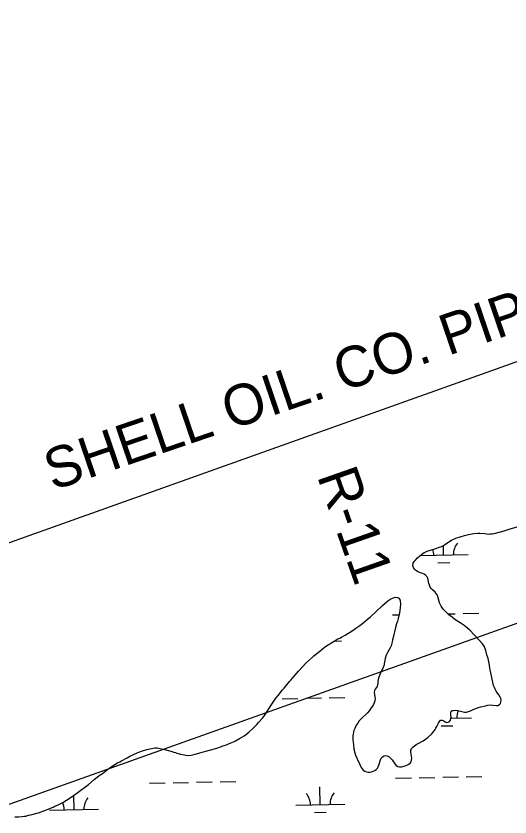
# Model space of a CAD drawing. Extents: x 3989314 to 4027622, y 243956 to 270014.
# Drawn here: x 3999415 to 4000421, y 258108 to 259739 of the extents above; entities that cross this region are included whole.
import ezdxf

# ---------------------------------------------------------------- set-up
doc = ezdxf.new("R2010")
doc.units = 0
for name, color, linetype in [('V-RIVR-EDGE', 7, 'Continuous'), ('V-RIVR-RANG-IDEN', 7, 'Continuous'), ('V-UTIL-IDEN', 7, 'Continuous'), ('V-UTIL-LINE', 7, 'Continuous'), ('V-WETL-SWMP', 7, 'Continuous')]:
    doc.layers.add(name, color=color, linetype=linetype)

msp = doc.modelspace()

# ---------------------------------------------------------------- linework, layer by layer
at = {"layer": 'V-RIVR-EDGE'}
for points in [[(4000224.3, 258624.6), (4000226.1, 258628.2), (4000228.1, 258630.5), (4000233.1, 258635.6), (4000237.8, 258639.8), (4000240.9, 258642.4), (4000246.7, 258646.3), (4000249.5, 258647.8), (4000252.4, 258649), (4000270.4, 258654.7), (4000277.7, 258657.2), (4000281.6, 258658.8), (4000286, 258661), (4000289.8, 258663.3), (4000298.9, 258669.5), (4000302.2, 258671.6), (4000311.2, 258675.6), (4000319.9, 258678.6), (4000328.7, 258681.1), (4000336.5, 258683), (4000347.8, 258685.1), (4000355.3, 258685.7), (4000360.1, 258685.7), (4000369.9, 258684.9), (4000373.8, 258684.3), (4000377.8, 258684), (4000381.2, 258684.2), (4000385.2, 258684.5), (4000389.2, 258685.2), (4000401.7, 258688.4), (4000409.5, 258690.7), (4000419.9, 258694.2), (4000435.7, 258698.6)], [(4000244.1, 258262.5), (4000253.6, 258269.8), (4000261.7, 258277.3), (4000264.4, 258280), (4000266.8, 258282.9), (4000268.9, 258285.8), (4000270.5, 258288.4), (4000272.4, 258292.2), (4000275.6, 258299), (4000277.4, 258302.1), (4000279.6, 258304.7), (4000283, 258305.1), (4000286.2, 258303.9), (4000289.1, 258301.5), (4000291.8, 258300.2), (4000295.1, 258300.7), (4000298.2, 258302.1), (4000299.9, 258304.9), (4000300.8, 258308.2), (4000301.2, 258311.4), (4000300.8, 258315.1), (4000300.7, 258318.4), (4000301, 258321.9), (4000303.4, 258324.3), (4000307.2, 258324.8), (4000310.5, 258325.1), (4000315, 258324.7), (4000328.7, 258321.3), (4000332.6, 258321.3), (4000340.9, 258323.9), (4000344.9, 258325.8), (4000353.3, 258329.3), (4000357.3, 258330.6), (4000361.7, 258331.9), (4000368.3, 258333.3), (4000371.4, 258334.3), (4000375.9, 258335.4), (4000382.6, 258336), (4000386.1, 258335.8), (4000393.2, 258334.5), (4000396.7, 258335.1), (4000400.1, 258336.5), (4000402.1, 258338.7), (4000403, 258341.9), (4000403.2, 258345.4), (4000402.6, 258348.8), (4000401.4, 258352), (4000398.9, 258356.2), (4000395.8, 258360), (4000393, 258364.2), (4000390.8, 258368.3), (4000389.5, 258371.2), (4000387.9, 258375.4), (4000384.1, 258392.1), (4000382.4, 258401.5), (4000380.5, 258410.9), (4000379.6, 258417), (4000376.6, 258430.7), (4000374.3, 258438), (4000372.1, 258446.6), (4000370.7, 258450.5), (4000369.1, 258454.2), (4000367.3, 258457.6), (4000364.9, 258461.2), (4000359.5, 258467.3), (4000339.2, 258488.1), (4000331.3, 258495.2), (4000327.8, 258497.9), (4000324.1, 258500.6), (4000320.1, 258503.1), (4000309.1, 258510.3), (4000303.3, 258514.6), (4000297, 258519.8), (4000291.9, 258524.4), (4000286, 258530.6), (4000283.8, 258533.3), (4000281.2, 258537), (4000279, 258541), (4000277.9, 258544.1), (4000275.2, 258553.8), (4000274, 258557.3), (4000272.8, 258560.1), (4000268.8, 258565.7), (4000263.5, 258570.7), (4000261, 258573.4), (4000258.8, 258576.1), (4000257.1, 258579.6), (4000256.1, 258583.5), (4000254.8, 258590.5), (4000253.7, 258594.1), (4000252.2, 258597.2), (4000249.5, 258599.8), (4000246.4, 258602.1), (4000242.8, 258603.8), (4000237.1, 258606), (4000233.1, 258607.8), (4000229.5, 258609.9), (4000226.6, 258612.4), (4000224.4, 258615.7), (4000223.5, 258620.1), (4000224.3, 258624.6)], [(3999490.1, 258127.6), (3999493.5, 258129.4), (3999501.9, 258133.3), (3999509.7, 258137.3), (3999525.2, 258146.6), (3999538.8, 258155.9), (3999562, 258174.1), (3999573.7, 258184), (3999579.9, 258188.9), (3999584.3, 258192.3), (3999590.5, 258196.5), (3999600.7, 258204.5), (3999610.8, 258211.3), (3999621.5, 258217.7), (3999625.8, 258219.8), (3999629.5, 258222.1), (3999641.2, 258228.4), (3999647.6, 258232.2), (3999651.1, 258233.7), (3999654, 258235.3), (3999661.7, 258238.6), (3999664.8, 258239.9), (3999672.6, 258242.7), (3999681.2, 258245.3), (3999690.4, 258247.5), (3999697.6, 258248.4), (3999702, 258248.7), (3999720.1, 258244.5), (3999732.6, 258241), (3999735.6, 258240), (3999739.5, 258238.9), (3999742.3, 258237.9), (3999749.8, 258235.8), (3999757.6, 258234), (3999763.6, 258233.1), (3999771.8, 258233.9), (3999779.7, 258235.7), (3999796.7, 258240.7), (3999801.4, 258241.7), (3999818.9, 258246.4), (3999826.2, 258248.6), (3999829.3, 258249.9), (3999833.2, 258251.1), (3999836.1, 258252.4), (3999843.6, 258255), (3999847.8, 258256.8), (3999850.7, 258258.4), (3999857.7, 258260.8), (3999861.7, 258262.8), (3999870.1, 258267.5), (3999880.6, 258273.8), (3999890, 258281.2), (3999895.8, 258286.4), (3999903.5, 258294), (3999905.5, 258296.2), (3999908.6, 258300.1), (3999916.9, 258309), (3999919.5, 258312.4), (3999924.8, 258320.2), (3999934.5, 258335.3), (3999944.3, 258349.4), (3999948.8, 258355.4), (3999958, 258366.5), (3999961.1, 258370), (3999966.6, 258376.9), (3999972.2, 258383.7), (3999975, 258386.7), (3999981.4, 258394.7), (3999990.3, 258405), (4000005.9, 258421.4), (4000011.9, 258427.2), (4000018.4, 258432.8), (4000021.8, 258435.9), (4000033.8, 258445.8), (4000043.5, 258453.3), (4000050.8, 258458.6), (4000059.4, 258463.9), (4000063, 258465.8), (4000069.3, 258469.6), (4000074.2, 258472.1), (4000077.6, 258474.2), (4000085.3, 258478.3), (4000099.6, 258486.7), (4000107.4, 258492), (4000115.2, 258497.7), (4000121.1, 258502.3), (4000130.8, 258510.5), (4000136.1, 258514.6), (4000148.4, 258526.3), (4000161.3, 258538.2), (4000172.7, 258547.9), (4000178.7, 258552), (4000185.6, 258554.7), (4000188.9, 258555.2), (4000192.1, 258554.9), (4000194.8, 258553.2), (4000196.7, 258550.6), (4000197.6, 258547.6), (4000198.2, 258541.9), (4000197.6, 258533.8), (4000196.1, 258523.3)], [(4000196.1, 258523.3), (4000193.5, 258511.8), (4000191.9, 258506.8), (4000189.9, 258501.2), (4000187.7, 258493.5), (4000183, 258473.5), (4000182, 258468.7), (4000181.3, 258464.4), (4000179.2, 258456.4), (4000177.4, 258452.2), (4000171.5, 258442.5), (4000169.4, 258438.6), (4000168, 258435), (4000166.7, 258430.3), (4000164.1, 258415.4), (4000163.1, 258412), (4000161, 258407.7), (4000157.2, 258401.3), (4000153.9, 258392.5), (4000152.6, 258388.1), (4000152.1, 258384.4), (4000151.9, 258380.2), (4000151.4, 258377.1), (4000150.4, 258373.5), (4000148.7, 258370.7), (4000146.6, 258368.1), (4000145.1, 258365.3), (4000144.7, 258361.6), (4000145.2, 258357.5), (4000146.1, 258352.7), (4000146.4, 258348.6), (4000145.7, 258344.2), (4000144.4, 258339.9), (4000142.9, 258336.8), (4000140.4, 258332.7), (4000137.3, 258328.2), (4000134.7, 258324.8), (4000129.9, 258319.1), (4000118.5, 258308.3), (4000116.5, 258306.1), (4000114, 258303.3), (4000111.1, 258299.1), (4000108.1, 258294.5), (4000105, 258288), (4000103.4, 258283.9), (4000102.3, 258280.4), (4000101.6, 258276.7), (4000101.1, 258272.7), (4000101.1, 258264.7), (4000101.5, 258259.2), (4000102.1, 258255.5), (4000103.3, 258246), (4000105.2, 258238.6), (4000106.7, 258233.5), (4000109.7, 258226.3), (4000115.3, 258214.4), (4000116.8, 258211.4), (4000117.8, 258208.6), (4000119.9, 258205.6), (4000122.2, 258203.3), (4000125.5, 258200.9), (4000128.7, 258199.5), (4000132, 258198.9), (4000135.8, 258199.3), (4000138.9, 258199.9), (4000142.4, 258200.9), (4000146, 258202.5), (4000148.6, 258204.7), (4000151.3, 258207.3), (4000152.8, 258210.1), (4000154.3, 258213.3), (4000157.4, 258224.1), (4000159.1, 258227.3), (4000161.8, 258229.9), (4000165, 258232.1), (4000168.2, 258233), (4000171.3, 258232.2), (4000175.2, 258229.9), (4000178.9, 258226.4), (4000181.1, 258223.8), (4000184, 258220), (4000186.4, 258216.3), (4000189.5, 258212.7), (4000192.9, 258210.5), (4000196.4, 258209.8), (4000200.3, 258209.8), (4000207.6, 258211.6), (4000211.4, 258213), (4000215.1, 258215.2), (4000217.6, 258217.4), (4000219.6, 258220.1), (4000220.8, 258223.2), (4000221.2, 258227.4), (4000219.1, 258239.6), (4000219.5, 258243.4), (4000220.9, 258246.9), (4000223.5, 258249.8), (4000225.7, 258251.9), (4000230, 258255.1), (4000232.7, 258256.7), (4000244.1, 258262.5)], [(3999411.8, 258108.2), (3999419.7, 258107.8), (3999427.2, 258108.4), (3999431.2, 258109.1), (3999434.8, 258109.7), (3999439.7, 258111.1), (3999445, 258112.3), (3999457.1, 258115.6), (3999460.1, 258116.3), (3999474.8, 258121.3), (3999490.1, 258127.6)]]:
    msp.add_lwpolyline(points, dxfattribs=at)
at = {"layer": 'V-UTIL-LINE'}
for points in [[(3993476.2, 256555.4), (4009243.9, 262176.3), (4010284.4, 262316.3), (4011271.4, 262462.6)], [(4011371.2, 261859.1), (4011335.1, 261835.4), (4010585.7, 261810.1), (4009561, 261669.6), (4009556.2, 261668.8), (4009323.1, 261637.1), (4006559.3, 260668.5), (4004279, 259872), (3996043.1, 256937.7), (3993486.8, 256012.2)]]:
    msp.add_lwpolyline(points, dxfattribs=at)
at = {"layer": 'V-WETL-SWMP'}
for p, q in [((4000286.1, 258641.4), (4000285.7, 258660.8)), ((4000238.5, 258640.5), (4000336.1, 258642.4)), ((4000274.4, 258625.7), (4000298.4, 258626.2)), ((4000181.6, 258519.2), (4000195.2, 258519.5)), ((4000295.1, 258521.5), (4000309.6, 258521.8)), ((4000325.6, 258522.1), (4000357.6, 258522.7)), ((4000063.5, 258466.1), (4000078.1, 258466.4)), ((4000039.5, 258450.2), (4000040.4, 258450.2)), ((4000053, 258350.5), (4000085, 258351.1)), ((3999957, 258348.5), (3999989, 258349.2)), ((4000005, 258349.5), (4000037, 258350.1)), ((4000300.9, 258309), (4000342.7, 258309.8)), ((4000281, 258293.1), (4000305, 258293.6)), ((4000188.3, 258186.6), (4000220.3, 258187.3)), ((4000236.3, 258187.6), (4000268.3, 258188.2)), ((4000284.3, 258188.5), (4000316.2, 258189.2)), ((4000332.2, 258189.5), (4000364.2, 258190.1)), ((3999686.5, 258176.6), (3999718.5, 258177.3)), ((3999734.5, 258177.6), (3999766.4, 258178.2)), ((3999782.4, 258178.5), (3999814.4, 258179.2)), ((3999830.4, 258179.5), (3999862.4, 258180.1)), ((4000034.7, 258132.8), (4000034, 258168.8)), ((3999532.9, 258122.8), (3999532.3, 258151.5)), ((3999482.9, 258121.8), (3999582.9, 258123.8)), ((3999984.7, 258131.8), (4000084.7, 258133.8)), ((4000023, 258117.1), (4000047, 258117.6))]:
    msp.add_line(p, q, dxfattribs=at)
for points in [[(4000224.3, 258624.6), (4000226.1, 258628.2), (4000228.1, 258630.5), (4000233.1, 258635.6), (4000237.8, 258639.8), (4000240.9, 258642.4), (4000246.7, 258646.3), (4000249.5, 258647.8), (4000252.4, 258649), (4000270.4, 258654.7), (4000277.7, 258657.2), (4000281.6, 258658.8), (4000286, 258661), (4000289.8, 258663.3), (4000298.9, 258669.5), (4000302.2, 258671.6), (4000311.2, 258675.6), (4000319.9, 258678.6), (4000328.7, 258681.1), (4000336.5, 258683), (4000347.8, 258685.1), (4000355.3, 258685.7), (4000360.1, 258685.7), (4000369.9, 258684.9), (4000373.8, 258684.3), (4000377.8, 258684), (4000381.2, 258684.2), (4000385.2, 258684.5), (4000389.2, 258685.2), (4000401.7, 258688.4), (4000409.5, 258690.7), (4000419.9, 258694.2), (4000435.7, 258698.6)], [(4000244.1, 258262.5), (4000253.6, 258269.8), (4000261.7, 258277.3), (4000264.4, 258280), (4000266.8, 258282.9), (4000268.9, 258285.8), (4000270.5, 258288.4), (4000272.4, 258292.2), (4000275.6, 258299), (4000277.4, 258302.1), (4000279.6, 258304.7), (4000283, 258305.1), (4000286.2, 258303.9), (4000289.1, 258301.5), (4000291.8, 258300.2), (4000295.1, 258300.7), (4000298.2, 258302.1), (4000299.9, 258304.9), (4000300.8, 258308.2), (4000301.2, 258311.4), (4000300.8, 258315.2), (4000300.7, 258318.4), (4000301, 258321.9), (4000303.4, 258324.3), (4000307.2, 258324.8), (4000310.5, 258325.1), (4000315, 258324.7), (4000328.7, 258321.3), (4000332.6, 258321.3), (4000340.9, 258323.9), (4000344.9, 258325.8), (4000353.3, 258329.3), (4000357.3, 258330.6), (4000361.7, 258331.9), (4000368.3, 258333.3), (4000371.4, 258334.3), (4000375.9, 258335.4), (4000382.6, 258336), (4000386.1, 258335.8), (4000393.2, 258334.5), (4000396.7, 258335.1), (4000400.1, 258336.5), (4000402.1, 258338.7), (4000403, 258341.9), (4000403.2, 258345.4), (4000402.6, 258348.8), (4000401.4, 258352), (4000398.9, 258356.2), (4000395.8, 258360), (4000393, 258364.2), (4000390.8, 258368.3), (4000389.5, 258371.2), (4000387.9, 258375.4), (4000384.1, 258392.1), (4000382.4, 258401.5), (4000380.5, 258410.9), (4000379.6, 258417), (4000376.6, 258430.7), (4000374.3, 258438), (4000372.1, 258446.6), (4000370.7, 258450.5), (4000369.1, 258454.2), (4000367.3, 258457.6), (4000364.9, 258461.2), (4000359.5, 258467.3), (4000339.2, 258488.1), (4000331.3, 258495.2), (4000327.8, 258497.9), (4000324.1, 258500.6), (4000320.1, 258503.1), (4000309.1, 258510.3), (4000303.3, 258514.6), (4000297, 258519.8), (4000291.9, 258524.4), (4000286, 258530.6), (4000283.8, 258533.3), (4000281.2, 258537), (4000279, 258541), (4000277.9, 258544.1), (4000275.2, 258553.8), (4000274, 258557.3), (4000272.8, 258560.1), (4000268.8, 258565.7), (4000263.5, 258570.7), (4000261, 258573.4), (4000258.8, 258576.1), (4000257.1, 258579.6), (4000256.1, 258583.5), (4000254.8, 258590.5), (4000253.7, 258594.1), (4000252.2, 258597.2), (4000249.5, 258599.8), (4000246.4, 258602.1), (4000242.8, 258603.8), (4000237.1, 258606), (4000233.1, 258607.8), (4000229.5, 258609.9), (4000226.6, 258612.4), (4000224.4, 258615.7), (4000223.5, 258620.1), (4000224.3, 258624.6)], [(3999490.1, 258127.6), (3999493.5, 258129.4), (3999501.9, 258133.3), (3999509.7, 258137.3), (3999525.2, 258146.6), (3999538.8, 258155.9), (3999562, 258174.1), (3999573.7, 258184), (3999579.9, 258188.9), (3999584.3, 258192.3), (3999590.5, 258196.5), (3999600.7, 258204.5), (3999610.8, 258211.3), (3999621.5, 258217.7), (3999625.8, 258219.8), (3999629.5, 258222.1), (3999641.2, 258228.4), (3999647.6, 258232.2), (3999651.1, 258233.7), (3999654, 258235.3), (3999661.7, 258238.6), (3999664.8, 258239.9), (3999672.6, 258242.7), (3999681.2, 258245.3), (3999690.4, 258247.5), (3999697.6, 258248.4), (3999702, 258248.7), (3999720.1, 258244.5), (3999732.6, 258241), (3999735.6, 258240), (3999739.5, 258238.9), (3999742.3, 258237.9), (3999749.8, 258235.8), (3999757.6, 258234), (3999763.6, 258233.1), (3999771.8, 258233.9), (3999779.7, 258235.7), (3999796.7, 258240.7), (3999801.4, 258241.7), (3999818.9, 258246.4), (3999826.2, 258248.6), (3999829.3, 258249.9), (3999833.2, 258251.1), (3999836.1, 258252.4), (3999843.6, 258255), (3999847.8, 258256.8), (3999850.7, 258258.4), (3999857.7, 258260.8), (3999861.7, 258262.8), (3999870.1, 258267.5), (3999880.6, 258273.8), (3999890, 258281.2), (3999895.8, 258286.4), (3999903.5, 258294), (3999905.5, 258296.2), (3999908.6, 258300.1), (3999916.9, 258309), (3999919.5, 258312.4), (3999924.8, 258320.2), (3999934.5, 258335.3), (3999944.3, 258349.4), (3999948.8, 258355.4), (3999958, 258366.5), (3999961.1, 258370), (3999966.6, 258376.9), (3999972.2, 258383.7), (3999975, 258386.7), (3999981.4, 258394.7), (3999990.3, 258405), (4000005.9, 258421.4), (4000011.9, 258427.2), (4000018.4, 258432.8), (4000021.8, 258435.9), (4000033.8, 258445.8), (4000043.5, 258453.3), (4000050.8, 258458.6), (4000059.4, 258463.9), (4000063, 258465.8), (4000069.3, 258469.6), (4000074.2, 258472.1), (4000077.6, 258474.2), (4000085.3, 258478.3), (4000099.6, 258486.7), (4000107.4, 258492), (4000115.2, 258497.7), (4000121.1, 258502.3), (4000130.8, 258510.5), (4000136.1, 258514.6), (4000148.4, 258526.3), (4000161.3, 258538.2), (4000172.7, 258547.9), (4000178.7, 258552), (4000185.6, 258554.7), (4000188.9, 258555.2), (4000192.1, 258554.9), (4000194.8, 258553.2), (4000196.7, 258550.6), (4000197.6, 258547.6), (4000198.2, 258541.9), (4000197.6, 258533.8), (4000196.1, 258523.3)], [(4000196.1, 258523.3), (4000193.5, 258511.8), (4000191.9, 258506.8), (4000189.9, 258501.2), (4000187.7, 258493.5), (4000183, 258473.5), (4000182, 258468.7), (4000181.3, 258464.4), (4000179.2, 258456.4), (4000177.4, 258452.2), (4000171.5, 258442.5), (4000169.4, 258438.6), (4000168, 258435), (4000166.7, 258430.3), (4000164.1, 258415.4), (4000163.1, 258412), (4000161, 258407.7), (4000157.2, 258401.3), (4000153.9, 258392.5), (4000152.6, 258388.1), (4000152.1, 258384.4), (4000151.9, 258380.2), (4000151.4, 258377.1), (4000150.4, 258373.5), (4000148.7, 258370.7), (4000146.6, 258368.1), (4000145.1, 258365.3), (4000144.7, 258361.6), (4000145.2, 258357.5), (4000146.1, 258352.7), (4000146.4, 258348.6), (4000145.7, 258344.2), (4000144.4, 258339.9), (4000142.9, 258336.8), (4000140.4, 258332.7), (4000137.3, 258328.2), (4000134.7, 258324.8), (4000129.9, 258319.1), (4000118.5, 258308.3), (4000116.5, 258306.1), (4000114, 258303.3), (4000111.1, 258299.1), (4000108.1, 258294.5), (4000105, 258288), (4000103.4, 258283.9), (4000102.3, 258280.4), (4000101.6, 258276.7), (4000101.1, 258272.7), (4000101.1, 258264.7), (4000101.5, 258259.2), (4000102.1, 258255.5), (4000103.3, 258246), (4000105.2, 258238.6), (4000106.7, 258233.5), (4000109.7, 258226.3), (4000115.3, 258214.4), (4000116.8, 258211.4), (4000117.8, 258208.6), (4000119.9, 258205.6), (4000122.2, 258203.3), (4000125.5, 258200.9), (4000128.7, 258199.5), (4000132, 258198.9), (4000135.8, 258199.3), (4000138.9, 258199.9), (4000142.4, 258200.9), (4000146, 258202.5), (4000148.6, 258204.7), (4000151.3, 258207.3), (4000152.8, 258210.1), (4000154.3, 258213.3), (4000157.4, 258224.1), (4000159.1, 258227.3), (4000161.8, 258229.9), (4000165, 258232.1), (4000168.2, 258233), (4000171.3, 258232.2), (4000175.2, 258229.9), (4000178.9, 258226.4), (4000181.1, 258223.8), (4000184, 258220), (4000186.4, 258216.3), (4000189.5, 258212.7), (4000192.9, 258210.5), (4000196.4, 258209.8), (4000200.3, 258209.8), (4000207.6, 258211.6), (4000211.4, 258213), (4000215.1, 258215.2), (4000217.6, 258217.4), (4000219.6, 258220.1), (4000220.8, 258223.2), (4000221.2, 258227.4), (4000219.1, 258239.6), (4000219.5, 258243.4), (4000220.9, 258246.9), (4000223.5, 258249.8), (4000225.7, 258251.9), (4000230, 258255.1), (4000232.7, 258256.7), (4000244.1, 258262.5)], [(3999411.8, 258108.2), (3999419.7, 258107.8), (3999427.2, 258108.4), (3999431.2, 258109.1), (3999434.8, 258109.7), (3999439.7, 258111.1), (3999445, 258112.3), (3999457.1, 258115.6), (3999460.1, 258116.3), (3999474.8, 258121.3), (3999490.1, 258127.6)]]:
    msp.add_lwpolyline(points, dxfattribs=at)
for centre, start, end in [((4000341.3, 258643), 140.3699, 181.9135), ((4000230.8, 258640.8), 0.3699, 19.6625), ((4000347.9, 258310.4), 156.2855, 181.9135), ((3999979.5, 258132.2), 0.3699, 41.9135), ((4000089.9, 258134.4), 140.3699, 181.9135), ((3999588.1, 258124.4), 140.3699, 181.9135), ((3999477.7, 258122.2), 0.3699, 25.2378)]:
    msp.add_arc(centre, 35.2, start, end, dxfattribs=at)

# ---------------------------------------------------------------- texts
at = {"layer": 'V-RIVR-RANG-IDEN'}
msp.add_text('R-11 ', height=83, rotation=289.2916, dxfattribs=at).set_placement((4000027.5, 258802.8))
at = {"layer": 'V-UTIL-IDEN'}
msp.add_text('SHELL OIL. CO. PIPELINES', height=83, rotation=18.8423, dxfattribs=at).set_placement((3999489.5, 258772.1))

doc.saveas('drawing.dxf')
